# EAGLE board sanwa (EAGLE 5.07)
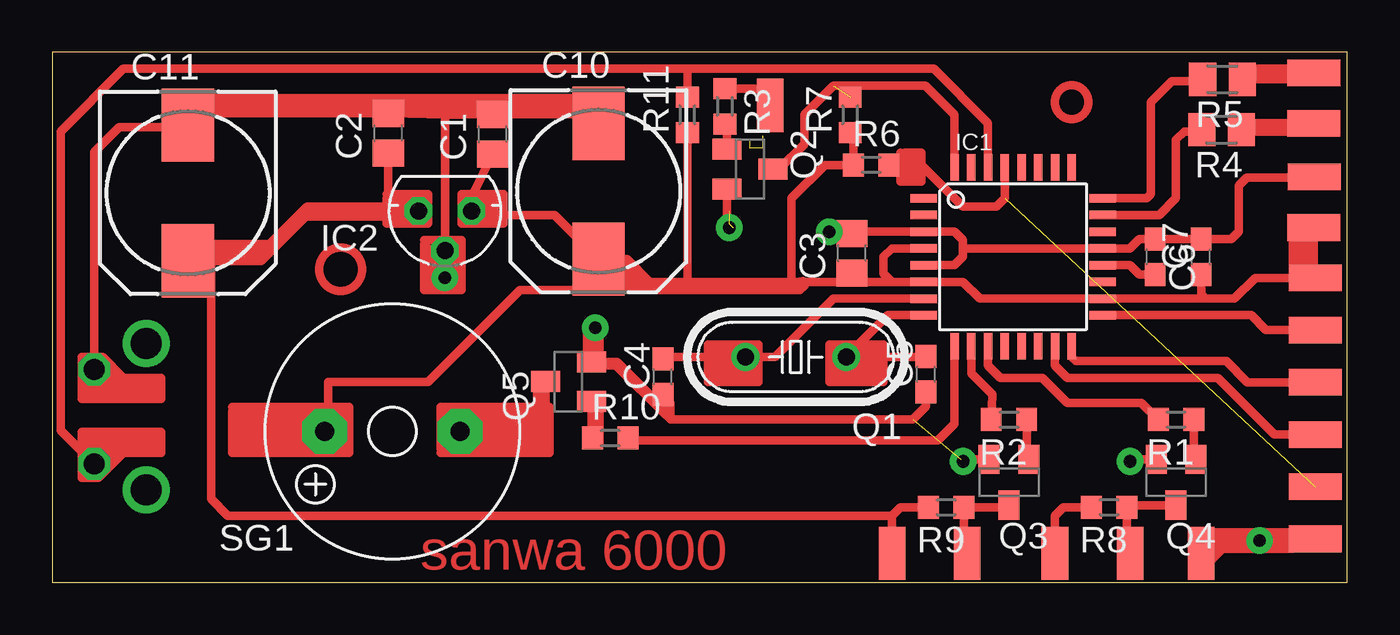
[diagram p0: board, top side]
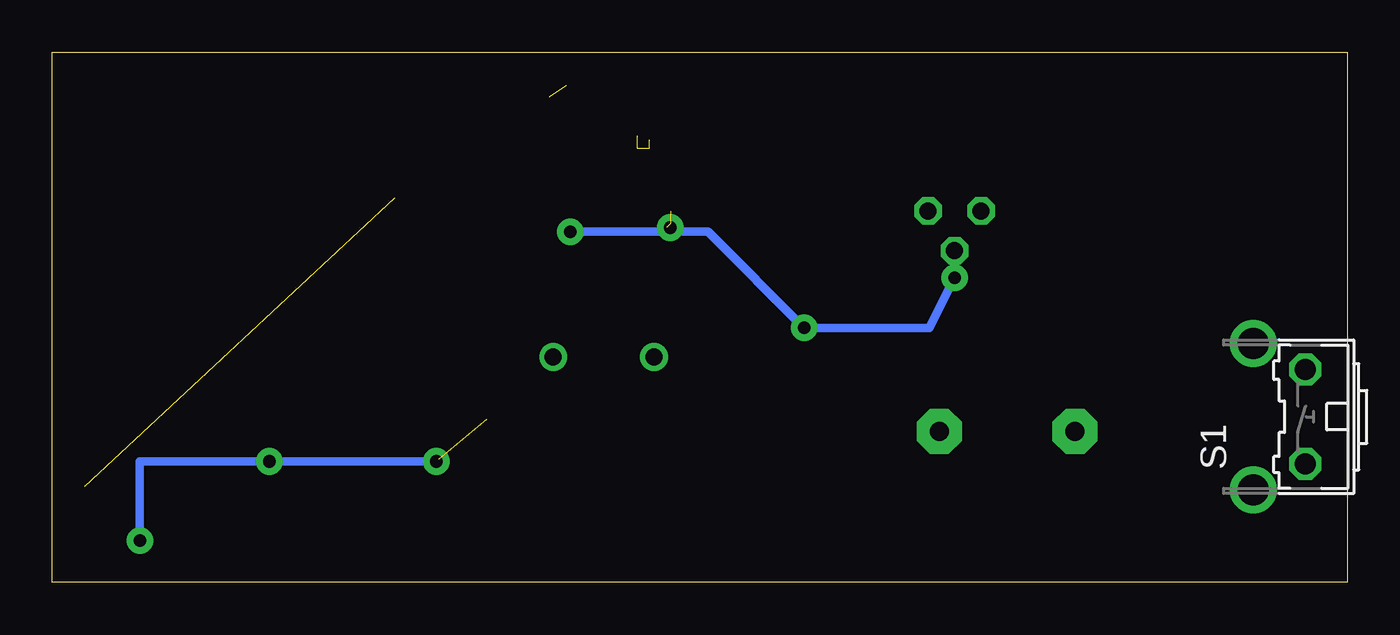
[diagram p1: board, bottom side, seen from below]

Size 62 x 25.4 mm. Coordinates in mm from the lower left corner, seen from the top.
Outline: 0,0 62,0 62,25.4 0,25.4 0,0
Copper layers (1*16): Top 0.035mm / dielectric 1.5mm / Bottom 0.035mm
Design rules "default": minimum track width 10mil, minimum drill 24mil, track to track 8mil, track to pad 8mil, pad to pad 8mil, via to via 8mil, smd to smd 8mil, copper to edge 40mil, drill to drill 8mil, minimum pad ring 10mil, minimum via ring 8mil, stop-mask expansion 4mil, vias tented up to drill 0mil, thermal gap 10mil

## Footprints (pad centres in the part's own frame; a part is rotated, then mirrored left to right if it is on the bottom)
C0805 = smd 1.3 x 1.5: 1 -0.95,0; 2 0.95,0
C0603 = smd 1.1 x 1: 1 -0.85,0; 2 0.85,0
150CLZ-0810 = smd 3.5 x 2.5: + 3.25,0; - -3.25,0
TQFP32-08-04 = smd 1.27 x 0.406: 1 -4.293,2.8; 2 -4.293,2; 3 -4.293,1.2; 4 -4.293,0.4; 5 -4.293,-0.4; 6 -4.293,-1.2; 7 -4.293,-2; 8 -4.293,-2.8; 17 4.293,-2.8; 18 4.293,-2; 19 4.293,-1.2; 20 4.293,-0.4; 21 4.293,0.4; 22 4.293,1.2; 23 4.293,2; 24 4.293,2.8 | smd 0.406 x 1.27: 9 -2.8,-4.293; 10 -2,-4.293; 11 -1.2,-4.293; 12 -0.4,-4.293; 13 0.4,-4.293; 14 1.2,-4.293; 15 2,-4.293; 16 2.8,-4.293; 25 2.8,4.293; 26 2,4.293; 27 1.2,4.293; 28 0.4,4.293; 29 -0.4,4.293; 30 -1.2,4.293; 31 -2,4.293; 32 -2.8,4.293
78LXX = drill 0.813 octagon: GND 0,1.905; IN 1.27,0; OUT -1.27,0
HC49/S = drill 0.813 round: 1 -2.413,0; 2 2.413,0
SOT23-BEC = smd 1 x 1.4: B -0.95,-1.1; C 0,1.1; E 0.95,-1.1
R0603 = smd 1 x 1.1: 1 -0.85,0; 2 0.85,0
M0805 = smd 1.3 x 1.6: 1 -0.95,0; 2 0.95,0
B3F-31XX = drill 1.016 octagon: 1 -2.261,-1.245; 2 2.261,-1.245 | drill 1.499 pad 2.159 round: 3 -3.505,1.245; 4 3.505,1.245
F/QMX = drill 0.914 pad 2.159 octagon: + 3.251,0; - -3.251,0
1PIN = smd 2.54 x 1.27: P$1 0,0
6PIN = smd 2.54 x 1.27: P$7 -0.04,6.25; P$8 -0.04,3.75; P$9 -0.04,1.25; P$10 -0.04,-1.25; P$11 -0.04,-3.75; P$12 -0.04,-6.25

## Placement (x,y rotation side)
C1  100n  [C0805]  21.08,21.47 90 top
C2  100n  [C0805]  16.08,21.52 90 top
C3  100n  [C0805]  38.28,15.77 90 top
C4  22p  [C0603]  29.23,9.85 90 top
C5  22p  [C0603]  41.83,9.97 90 top
C6  100n  [C0603]  52.8,15.6 270 top
C7  100n  [C0603]  55,15.6 90 top
C10  [150CLZ-0810]  26.15,18.74 270 top
C11  [150CLZ-0810]  6.49,18.66 270 top
IC1  MEGA8-AI  [TQFP32-08-04]  46,15.6 0 top
IC2  [78LXX]  18.8,17.8 180 top
Q1  12MHz  [HC49/S]  35.6,10.8 180 top
Q2  BC849SMD  [SOT23-BEC]  33.4,19.8 270 top
Q3  BC849SMD  [SOT23-BEC]  45.8,4.8 180 top
Q4  BC849SMD  [SOT23-BEC]  53.8,4.8 180 top
Q5  BC849SMD  [SOT23-BEC]  24.71,9.62 90 top
R1  4.7  [R0603]  53.8,7.8 180 top
R2  4.7k  [R0603]  45.8,7.8 180 top
R3  4.7k  [R0603]  32.2,22.8 270 top
R4  0  [M0805]  55.98,21.69 180 top
R5  0  [M0805]  56.02,24.1 180 top
R6  10k  [R0603]  39.2,20 0 top
R7  10k  [R0603]  38.2,22.4 90 top
R8  10k  [R0603]  50.6,3.6 180 top
R9  10k  [R0603]  42.8,3.6 180 top
R10  4.7  [R0603]  26.72,6.92 0 top
R11  1k  [R0603]  30.4,22.4 90 top
S1  [B3F-31XX]  3.25,7.94 90 bottom
SG1  F/QMX  [F/QMX]  16.28,7.24 180 top
U$1  1PIN  [1PIN]  34.38,22.85 270 top
U$2  1PIN  [1PIN]  51.6,1.4 90 top
U$3  6PIN6  [6PIN]  60.43,8.34 180 top
U$4  1PIN  [1PIN]  43.8,1.4 90 top
U$5  1PIN  [1PIN]  40.2,1.4 90 top
U$6  1PIN  [1PIN]  55,1.4 90 top
U$7  1PIN  [1PIN]  60.4,22 0 top
U$8  1PIN  [1PIN]  60.4,24.4 180 top
U$9  1PIN  [1PIN]  60.41,19.43 180 top
U$10  1PIN  [1PIN]  60.4,17 180 top
U$11  1PIN  [1PIN]  48,1.4 90 top

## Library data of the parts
C1-C7 C10 C11 R1-R11 = rcl
IC1 = atmel
IC2 = v-reg
Q1 = crystal
Q2-Q5 = transistor-npn
S1 = switch-omron
SG1 = buzzer
U$1-U$11 = 001xx

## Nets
+5V: C1.1 C3.1 C7.1 C10.+ IC1.4 IC1.6 IC1.18 IC2.OUT R6.1 R7.1 R11.1 SG1.+ U$3.P$12 U$10.P$1
+12V: C2.1 C11.+ IC2.IN R9.2 U$5.P$1
GND: C1.2 C2.2 C3.2 C4.1 C5.1 C6.1 C7.2 C10.- C11.- IC1.3 IC1.5 IC1.21 IC2.GND Q2.E Q3.E Q4.E Q5.E S1.2 U$3.P$7 U$6.P$1 U$9.P$1
N$1: Q5.B R10.1
N$3: IC1.15 U$3.P$9
N$4: IC1.17 U$3.P$11
N$5: Q2.B R3.2
N$6: IC1.16 U$3.P$10
N$7: IC1.29 R6.2 U$3.P$8
N$8: IC1.30 R11.2 S1.1
N$9: IC1.11 R1.2
N$10: Q4.B R1.1
N$11: R3.1 U$1.P$1
N$12: R8.2 U$11.P$1
N$13: R4.1 U$7.P$1
N$14: IC1.23 R4.2
N$15: IC1.24 R5.2
N$16: IC1.9 R10.2
N$17: Q4.C R8.1 U$2.P$1
N$18: IC1.10 R2.2
N$19: Q3.B R2.1
N$20: Q3.C R9.1 U$4.P$1
N$22: C4.2 IC1.7 Q1.2
N$23: C5.2 IC1.8 Q1.1
N$24: R5.1 U$8.P$1
N$26: Q5.C SG1.-
N$27: C6.2 IC1.20
N$28: IC1.32 Q2.C R7.2

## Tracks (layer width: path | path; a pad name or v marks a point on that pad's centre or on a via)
+5V
  Top 0.406: 55.2,13.6 IC1.18 44.4,13.6 43.6,14.4 IC1.6 40.2,14.4 | 55.2,13.6 56.6,13.6 57.59,14.59 U$3.P$12 60.4,14.66 U$10.P$1 | C7.1 55,13.8 55.2,13.6 | 40.2,14.4 39.8,14.8 39.8,15.6 40.2,16 IC1.4 | 40.2,14.4 37.8,14.4 38.18,14.42 C3.1 37.66,14.4 35.6,14.4 | C10.+ 27.51,15.49 28.6,14.4 29.8,14.4 | 29.8,14.4 35.4,14.4 | 35.4,14.4 35.6,14.4 | 35.6,14.4 35.95,14.45 | C10.+ 26.2,15.44 | 19.8,17.6 24.04,17.6 C10.+ | 19.8,17.6 IC2.OUT | C1.1 19.68,17.68 19.8,17.6 | R7.1 38.35,21.55 R6.1 37,20 35.4,18.4 35.4,14.4 | R11.1 30.4,14.2 29.8,14.4 | SG1.+ 13.2,7.24 13.2,9.6 18,9.6 22.4,14 25.8,14 25.8,15.14 C10.+
+12V
  Top 0.406: 12.12,17.52 12.2,17.6 17.53,17.6 IC2.IN | 7.4,15.4 C11.+ | 7.4,15.4 10,15.4 12.1,17.5 12.12,17.52 | 16.08,17.52 C2.1 | 16.08,17.52 13,17.6 | R9.2 40.6,3.6 40.2,3.2 | 40.2,3.2 U$5.P$1 | 40.2,3.2 8.4,3.2 7.6,4 7.6,15.2 7.4,15.4 | 12.12,17.52 16.08,17.52
GND  (via drill 0.6 pad 1.27)  (1 unrouted)
  Top 0.406: S1.2 2,20.61 3.2,21.8 6.38,21.8 C11.- 6.2,22.2 6.2,22.8 6.53,22.47 C2.2 16.13,22.47 18.8,22.4 | IC1.5 43.2,15.2 43.6,15.6 43.6,16 | 43.6,16 43.6,16.4 43.2,16.8 IC1.3 38,16.8 37.92,16.72 | 43.6,16 IC1.21 51.6,16 52.05,16.45 C6.1 C7.2 56.45,16.45 56.8,16.8 56.8,19 57.2,19.4 60.38,19.4 U$9.P$1 | 37.92,16.72 C3.2 | C5.1 41.83,8.43 41.2,7.8 29.6,7.8 29.2,8.2 29.2,8.4 | 29.2,8.4 29.2,8.97 C4.1 | 26.15,21.65 C10.- 25.32,22.82 24.92,22.42 C1.2 19.66,22.4 18.8,22.4 | 18.8,22.4 IC2.GND 18.89,14.8 v18.8,14.6 | 26.4,10.57 Q5.E | 26.4,10.57 27.03,10.57 29.2,8.4 | 54.88,1.12 U$6.P$1 | 54.88,1.12 54.8,1.2 | 37.92,16.72 37.28,16.72 v37.2,16.8 | v26,12.2 26,10.97 26.4,10.57 | Q4.E 51.5,5.9 v51.6,5.8 | U$3.P$7 60.38,2 v57.8,2 56.4,2 55.52,1.12 54.88,1.12 | Q3.E 43.5,5.9 v43.6,5.8 | Q2.E 32.3,17.1 v32.4,17 | 17.8,16.4 19.6,16.4 19.6,14 17.8,14 17.8,16.2 18,16 18,14.4 18.2,14.2 19.4,14.2 19.4,15.8 19.2,16 18.2,16 18.2,14.4 19.2,14.4 19.2,15.8 18.4,15.8 18.4,14.6 v18.8,14.6 | v18.8,14.6 18.6,14.8 18.6,15.6
  Bottom 0.406: 32.4,16.8 30.6,16.8 v26,12.2 20,12.2 v18.8,14.6 | v57.8,2 57.8,5.8 v51.6,5.8 v43.6,5.8 | 32.4,16.8 v32.4,17 | 32.4,16.8 v37.2,16.8
N$1
  Top 0.406: Q5.B 25.81,6.98 R10.1
N$2
  Top 0.406: 40.6,20.6 40.6,19.2 41.6,19.2 41.6,20.6 41,20.6 | 40.8,20.6 41,20.6 | 41,20.6 41,19.4 41.2,19.4 41.2,20.2
N$3
  Top 0.406: U$3.P$9 58.51,7.09 55.8,9.8 48.6,9.8 48,10.4 IC1.15
N$4
  Top 0.406: U$3.P$11 58.11,12.09 57.4,12.8 IC1.17
N$5
  Top 0.406: Q2.B 32.3,21.85 R3.2
N$6
  Top 0.406: U$3.P$10 57.21,9.59 56.2,10.6 49,10.6 48.8,10.8 IC1.16
N$7  (1 unrouted)
  Top 0.406: IC1.29 45.6,18.4 45.2,18 43.6,18 41.4,20.2 41.4,20.55 R6.2
N$8
  Top 0.406: IC1.30 44.8,22 42.2,24.6 30.4,24.6 | 30.4,24.6 3.4,24.6 0.4,21.6 0.4,7.29 S1.1 | 30.4,24.6 R11.2
N$9
  Top 0.406: IC1.11 44.8,10.4 45.4,9.8 47.4,9.8 48.6,8.6 52.15,8.6 R1.2
N$10
  Top 0.406: R1.1 54.65,6 Q4.B
N$11
  Top 0.406: R3.1 33.75,23.65 33.8,23.6 34.2,23.43 U$1.P$1
N$12
  Top 0.406: R8.2 48.4,3.6 48,3.2 U$11.P$1
N$13
  Top 0.406: R4.1 57.09,21.69 57.4,22 U$7.P$1
N$14
  Top 0.406: IC1.23 53,17.6 53.8,18.4 53.8,21.2 54.2,21.6 54.94,21.6 R4.2
N$15
  Top 0.406: IC1.24 52.4,18.4 52.6,18.6 52.6,23 53.6,24 54.77,24 R5.2
N$16
  Top 0.406: IC1.9 43.2,7.6 42.4,6.8 27.69,6.8 R10.2
N$17
  Top 0.406: Q4.C 51.55,3.7 R8.1 51.45,1.15 U$2.P$1
N$18
  Top 0.406: R2.2 45,9 44,10 IC1.10
N$19
  Top 0.406: R2.1 46.65,6 Q3.B
N$20
  Top 0.406: U$4.P$1 43.65,1.35 R9.1 45.7,3.6 Q3.C
N$22
  Top 0.406: IC1.7 37.4,13.6 34.6,10.8 Q1.2 29.33,10.8 C4.2
N$23
  Top 0.406: Q1.1 38.01,10.81 | 38.01,10.81 38.6,11.4 | 38.6,11.4 40,12.8 IC1.8 | 38.01,10.81 C5.2 | 38.6,11.4 37.2,11.4 37.2,9.6 39.8,9.6 39.8,11.4 38.8,11.4 38.8,10 | 39,10 39.4,10 | 39.6,10 39.4,10 | 39.4,10 39.4,11.2 37.6,11.2 37.6,9.8 38,9.8 38,11 38.4,11 38.4,10 | 38.4,10 38.2,10 | 38.4,10 38.8,10 | 38.8,10 39,10 | 39,10 39,10.6
N$24
  Top 0.406: R5.1 59.9,24.1 U$8.P$1
N$26
  Top 0.406: Q5.C 23.61,7.21 23.6,7.2 19.57,7.2 SG1.-
N$27
  Top 0.406: C6.2 52.05,14.75 51.6,15.2 IC1.20
N$28  (1 unrouted)
  Top 0.406: IC1.32 43.2,22.4 41.8,23.8 37.4,23.8 36,22.4 36,21 34.8,19.8 Q2.C
N$29
  Top 0.406: 32.6,9.6 33.8,9.6 33.8,11.4 33.4,11.4 | 32.2,9.6 31.4,9.6 31.4,11.4 33.4,11.4 | 33.4,11.4 33.4,9.8 33,9.8 33,11.2 32.6,11.2 32.6,9.6 | 32.6,9.6 32.2,9.6 | 32.2,9.6 32.2,11.2 31.8,11.2 31.8,9.8
N$30
  Top 0.406: 23.6,8.4 18.6,8.4 18.6,7 | 23.6,8.4 23.6,8 18.6,8 18.6,7.6 23.6,7.6 23.6,6.8 | 23.6,6.8 18.6,6.8 | 18.6,6.8 18.6,7 | 18.6,6.8 18.6,6.4 23.6,6.4 | 23.6,6.4 23.6,6.8 | 23.6,6.4 23.6,6.2 | 23.6,6.2 23.2,6.2 | 23.2,6.2 19.2,6.2 | 18.6,6.2 19.2,6.2 | 19.2,6.2 19.2,7.4 19.4,7.4 19.4,7 18.6,7 | 23.6,8.4 23.8,8.4 23.8,6.2 23.6,6.2 | 23.2,6.2 23.2,9.2 23.4,9.2 23.4,9.4
N$31
  Top 0.406: 14,8.2 8.6,8.2 8.6,6.2 14.2,6.2 14.2,8.2 14,8.2 | 14,8.2 14,6.6 8.8,6.6 8.8,7.8 13.6,7.8 | 13.8,7.8 13.6,7.8 | 13.6,7.8 13.6,6.8 9.2,6.8 | 9,6.8 9.2,6.8 | 9.2,6.8 9.2,7.2 | 9.2,7.2 9.2,7.6 13.2,7.6 13.2,7.2 | 13.2,7.2 9.2,7.2 | 13.2,7.2 14.2,7.2 14.2,8.4 9.4,8.4 | 8.6,8.4 9.4,8.4 | 9.4,8.4 9.4,8
N$32
  Top 0.406: 2.2,10.8 2.4,10.8 3.4,9.8 5.2,9.8 5.2,9 | 5.2,9 1.4,9 | 1.4,9 1.4,10.8 2,10.8 2,9.4 1.8,9.2 1.8,10.6 2.2,10.6 3.4,9.4 | 3,9.4 2.2,9.4 | 3.4,9.4 5,9.4 | 3.4,9.4 3,9.4 | 3,9.4 2.2,10.2 2.2,9.8 2.4,9.6 | 1.4,9 1.4,8.8 5.2,8.8 5.2,9
N$33
  Top 0.406: 1.4,6.2 1.4,6.6 | 1.4,6.6 1.4,6.8 | 1.4,6.8 5.2,6.8 | 5.2,6.8 5.2,6.6 | 1.4,6.2 1.4,5 2.2,5 3.4,6.2 5.2,6.2 5.2,6.6 | 1.4,6.2 1.8,6.6 4.4,6.6 4.8,6.6 | 4.8,6.6 5,6.4 1.8,6.4 1.8,5.4 2.2,5.4 2.2,6.2 | 2.2,6.2 2.4,6.2 | 2.4,6.2 3,6.2 2.4,5.6 2.4,6.2 | 2.2,6.2 1.8,6.2 1.4,6.6 | 1.4,6.8 1.4,7.2 5.2,7.2 5.2,7 | 5.2,7 4.2,7 | 5.2,7 5.2,6.8 | 5.2,6.6 4.8,6.6
N$34
  Top 0.406: 25.6,12.2 25.6,11 26.2,11 26.2,11.8
N$35
  Top 0.406: 26.2,8.4 26.2,6.6
N$36
  Top 0.406: 29.6,8.6 29.6,8 29.4,8 27,10.4 26.6,10.4 26.4,10.4
N$37  (2 unrouted)
N$38
  Top 0.406: 7.4,15.8 10,15.8
N$41
  Top 0.406: 7.6,22.8 25.8,22.8
N$43
  Top 0.406: 27.2,15.4 27.4,15.4 28.6,14.2 28.6,14 | 27.2,15.2 28.4,14 | 28.4,14 28.6,14 | 28.6,14 35.8,14 36,14.2 | 28.4,14 27.4,14 | 27.2,14 27.4,14 | 27.4,14 27.8,14.4 27.6,14.4 27.4,14.6 27.6,14.6 28,14.2
N$45  (3 unrouted)
N$46
  Top 0.406: 55.4,2.4 59.4,2.4 59.4,1.6 55.4,1.6 55.4,1.8 55.8,2.2 56.2,2.2 | 56.4,2.2 56.2,2.2 | 56.2,2.2 55.8,1.8
N$47
  Top 0.406: 59.4,16.6 59.4,15 59.6,14.8 59.8,14.8 59.8,16.6 60.2,16.6 60.2,15
N$48
  Top 0.406: 57.4,21.6 59.4,21.6
N$49
  Top 0.406: 57.4,24.6 59.2,24.6 59.4,24.4 57.4,24.4
N$50
  Top 0.406: 7.6,23.2 25.2,23.2
S$3
  Top 0.406: 19.6,18.4 19.6,17.2 21.6,17.2 21.6,18.6 19.6,18.6 19.6,18.4 | 19.6,18.4 20.2,17.8 | 20.2,17.8 20.2,18.4 21.2,18.4 21.4,18.2 21.2,18 20.6,18 | 21.2,17.8 20.2,17.8
S$5
  Top 0.406: 16,18.6 18,18.6 18,18.4 | 10,16 10.2,16 10.4,16.2 | 10.6,16.4 12.2,18 18,18 18,17.4 16.8,17.4 16.8,18.2 18,18.2 18,18.4 | 18,18.4 16,18.4 16,17.2 18,17.2 18,17.6 17.8,17.8 | 7.4,16.2 10.4,16.2 | 10.4,16.2 10.6,16.4 | 10.6,16.4 10.8,16.4 11,16.6
(copper drawn outside any net)
  shapes: Top circle x2

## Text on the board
Top: sanwa 6000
